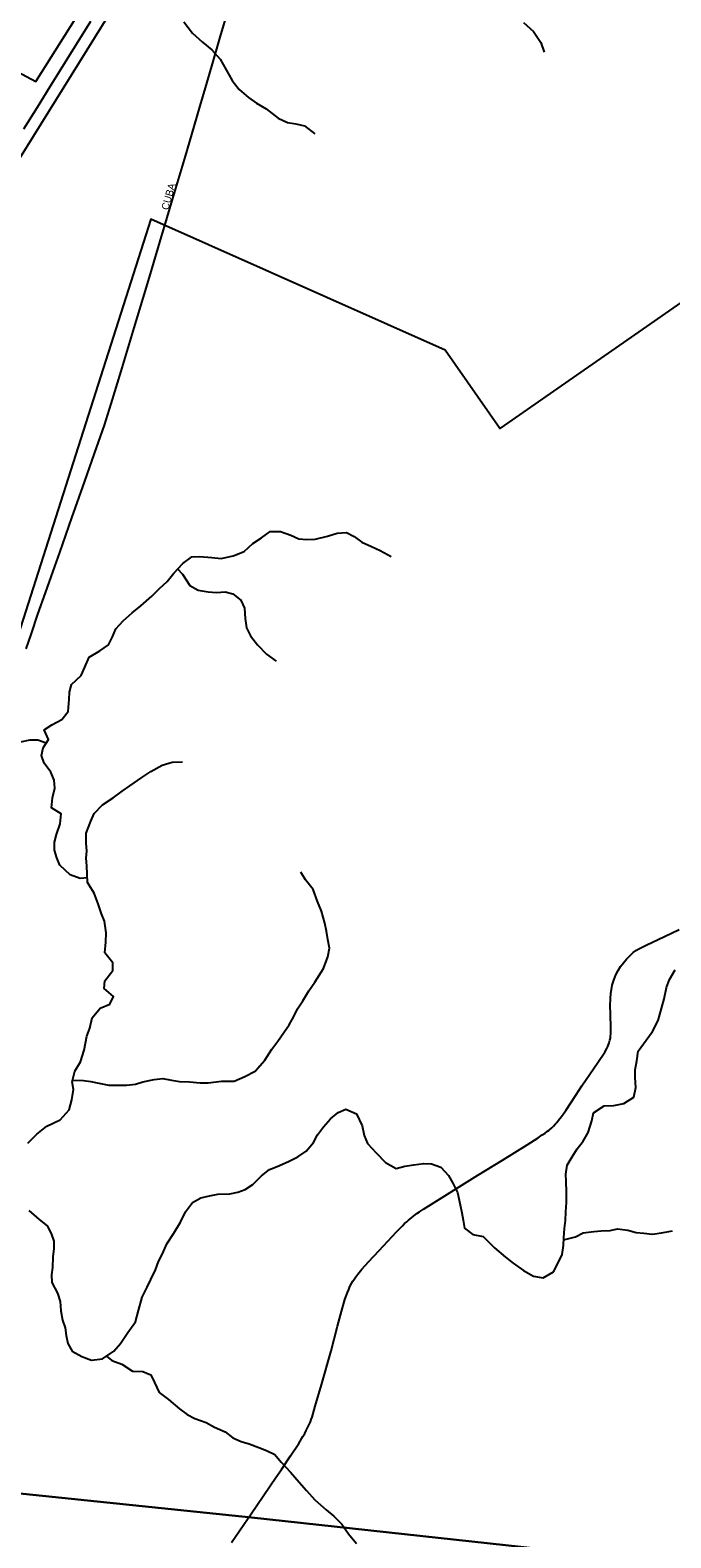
# Model space of a CAD drawing. Extents: x 1442749 to 1756758, y 235267 to 677782.
# Drawn here: x 1590164 to 1594524, y 510563 to 520821 of the extents above; entities that cross this region are included whole.
import ezdxf

# ---------------------------------------------------------------- set-up
doc = ezdxf.new("R2010")
doc.units = 0
for name, color, linetype in [('GM_X_City_Street', 7, 'Continuous'), ('GM_X_City_Street_Text', 7, 'Continuous'), ('GM_X_Corporation', 7, 'Continuous'), ('GM_X_County_Road', 7, 'Continuous'), ('GM_X_Major_River', 7, 'Continuous'), ('GM_X_Minor_River', 7, 'Continuous'), ('GM_X_Rail_Line', 7, 'Continuous'), ('GM_X_Township', 7, 'Continuous'), ('GM_X_Township_Road', 7, 'Continuous'), ('GM_X_US_Route', 7, 'Continuous')]:
    doc.layers.add(name, color=color, linetype=linetype)

msp = doc.modelspace()

# ---------------------------------------------------------------- linework, layer by layer
at = {"layer": 'GM_X_City_Street'}
msp.add_lwpolyline([(1591085, 519508), (1591125, 519647), (1591221, 519964), (1591279, 520166), (1591320, 520305), (1591356, 520428), (1591399, 520576), (1591457, 520774), (1591513, 520963)], dxfattribs=at)
at = {"layer": 'GM_X_Corporation'}
for points in [[(1600054, 522300), (1597344, 518704), (1597384, 518674), (1597022, 518194), (1596857, 518034), (1596225, 518761), (1595739, 518727), (1595708, 518852), (1595571, 518899), (1595536, 518975), (1595389, 518924), (1595223, 519406), (1593360, 518111), (1592987, 518643), (1590986, 519534), (1589824, 515905)], [(1589913, 520625), (1590202, 520471), (1591134, 521952)]]:
    msp.add_lwpolyline(points, dxfattribs=at)
at = {"layer": 'GM_X_County_Road'}
msp.add_lwpolyline([(1590136, 516611), (1590172, 516717), (1590217, 516847), (1590269, 516992), (1590321, 517141), (1590365, 517268), (1590448, 517503), (1590522, 517713), (1590616, 517979), (1590669, 518134), (1590715, 518278), (1590782, 518501), (1590872, 518796), (1590956, 519072), (1590994, 519201), (1591058, 519418), (1591085, 519508)], dxfattribs=at)
at = {"layer": 'GM_X_Major_River'}
for points in [[(1594203, 513518), (1594271, 513562), (1594286, 513626), (1594281, 513695), (1594281, 513747), (1594292, 513809), (1594301, 513875), (1594355, 513950), (1594398, 514007), (1594438, 514083), (1594460, 514165), (1594478, 514231), (1594495, 514308), (1594514, 514362), (1594554, 514428)], [(1590325, 512582), (1590324, 512532), (1590318, 512475), (1590315, 512403), (1590308, 512353), (1590311, 512301), (1590349, 512228), (1590368, 512171), (1590373, 512107), (1590383, 512043), (1590402, 511992), (1590409, 511940), (1590420, 511885), (1590449, 511832), (1590516, 511797), (1590582, 511771), (1590656, 511782), (1590733, 511834), (1590779, 511886), (1590828, 511959), (1590880, 512032), (1590902, 512110), (1590926, 512200), (1590959, 512269), (1590984, 512321), (1591016, 512387), (1591037, 512444), (1591064, 512496), (1591094, 512564), (1591142, 512635), (1591187, 512710), (1591221, 512780), (1591269, 512845), (1591325, 512876), (1591384, 512891), (1591442, 512901), (1591522, 512904), (1591577, 512915), (1591627, 512934), (1591678, 512967), (1591739, 513026), (1591793, 513069), (1591845, 513090), (1591922, 513124), (1591985, 513155), (1592042, 513194), (1592091, 513253), (1592120, 513305), (1592160, 513360), (1592207, 513413), (1592260, 513458), (1592313, 513479), (1592384, 513448), (1592422, 513367), (1592437, 513300), (1592460, 513245), (1592519, 513182), (1592581, 513116), (1592654, 513077), (1592713, 513091), (1592775, 513102), (1592842, 513111), (1592894, 513108), (1592959, 513084), (1593010, 513029), (1593041, 512976), (1593072, 512913), (1593090, 512829), (1593101, 512774), (1593110, 512724), (1593119, 512671), (1593176, 512628), (1593246, 512613), (1593324, 512537), (1593399, 512473), (1593450, 512432), (1593521, 512382), (1593590, 512344), (1593654, 512331), (1593725, 512374), (1593757, 512433), (1593784, 512491), (1593793, 512551), (1593795, 512605), (1593800, 512667), (1593807, 512723), (1593810, 512781), (1593814, 512845), (1593813, 512918), (1593811, 512988), (1593810, 513038), (1593819, 513098), (1593853, 513156), (1593886, 513209), (1593927, 513263), (1593961, 513322), (1593986, 513400), (1593998, 513454), (1594069, 513502), (1594135, 513505), (1594203, 513518)], [(1590155, 512790), (1590226, 512730), (1590279, 512685), (1590306, 512634), (1590325, 512582)]]:
    msp.add_lwpolyline(points, dxfattribs=at)
at = {"layer": 'GM_X_Minor_River'}
for points in [[(1591209, 520878), (1591269, 520801), (1591336, 520740), (1591401, 520687), (1591457, 520623), (1591498, 520552), (1591539, 520479), (1591585, 520417), (1591650, 520362), (1591704, 520325), (1591770, 520286), (1591851, 520223), (1591915, 520192), (1591971, 520183), (1592031, 520169), (1592102, 520116)], [(1593522, 520872), (1593590, 520811), (1593639, 520738), (1593662, 520672)], [(1590553, 515053), (1590503, 515049), (1590435, 515074), (1590366, 515139), (1590346, 515189), (1590329, 515242), (1590329, 515296), (1590342, 515348), (1590367, 515422), (1590374, 515490), (1590308, 515529), (1590315, 515599), (1590332, 515663), (1590326, 515719), (1590305, 515772), (1590258, 515834), (1590240, 515887), (1590253, 515939), (1590288, 515994), (1590260, 516061), (1590311, 516094), (1590379, 516130), (1590422, 516185), (1590429, 516266), (1590432, 516316), (1590446, 516368), (1590511, 516431), (1590536, 516487), (1590565, 516555), (1590637, 516598), (1590696, 516640), (1590723, 516694), (1590747, 516747), (1590796, 516803), (1590859, 516856), (1590918, 516904), (1590991, 516969), (1591045, 517023), (1591096, 517070), (1591141, 517126), (1591202, 517193), (1591264, 517237), (1591316, 517240), (1591401, 517233), (1591463, 517227), (1591545, 517244), (1591620, 517275), (1591678, 517328), (1591737, 517368), (1591796, 517411), (1591868, 517409), (1591937, 517384), (1591991, 517361), (1592047, 517356), (1592104, 517358), (1592188, 517379), (1592254, 517398), (1592317, 517403), (1592368, 517375), (1592420, 517338), (1592486, 517307), (1592546, 517280), (1592621, 517241)], [(1591167, 517155), (1591201, 517119), (1591250, 517042), (1591308, 517010), (1591374, 516999), (1591432, 516994), (1591490, 517000), (1591542, 516985), (1591598, 516942), (1591623, 516888), (1591628, 516818), (1591635, 516755), (1591663, 516699), (1591710, 516638), (1591772, 516575), (1591837, 516528)], [(1590272, 515970), (1590217, 515991), (1590161, 515990), (1590095, 515977), (1590027, 516003), (1589953, 516052), (1589900, 516079), (1589820, 516088), (1589755, 516079), (1589692, 516130), (1589624, 516148), (1589566, 516163), (1589510, 516168), (1589458, 516172), (1589404, 516181), (1589348, 516184), (1589290, 516188), (1589228, 516187), (1589177, 516186), (1589125, 516182), (1589067, 516205), (1589000, 516242), (1588928, 516277), (1588858, 516292)], [(1590147, 513248), (1590209, 513310), (1590278, 513363), (1590367, 513406), (1590430, 513474), (1590447, 513544), (1590458, 513614), (1590450, 513666), (1590467, 513738), (1590506, 513802), (1590531, 513882), (1590550, 513976), (1590569, 514030), (1590586, 514102), (1590641, 514167), (1590707, 514193), (1590730, 514246), (1590668, 514301), (1590673, 514353), (1590726, 514423), (1590726, 514475), (1590673, 514544), (1590678, 514616), (1590681, 514680), (1590670, 514759), (1590650, 514809), (1590627, 514877), (1590600, 514950), (1590555, 515021), (1590551, 515079), (1590550, 515135), (1590546, 515187), (1590549, 515237), (1590546, 515289), (1590544, 515358), (1590576, 515440), (1590600, 515491), (1590657, 515551), (1590728, 515598), (1590790, 515644), (1590843, 515679), (1590924, 515736), (1590986, 515778), (1591061, 515821), (1591131, 515840), (1591200, 515842)], [(1590453, 513678), (1590526, 513675), (1590576, 513667), (1590632, 513656), (1590698, 513643), (1590819, 513642), (1590881, 513649), (1590931, 513666), (1591008, 513682), (1591066, 513689), (1591126, 513678), (1591180, 513668), (1591248, 513665), (1591320, 513658), (1591374, 513659), (1591466, 513670), (1591551, 513671), (1591625, 513703), (1591696, 513738), (1591761, 513813), (1591808, 513889), (1591850, 513943), (1591889, 514002), (1591926, 514054), (1591959, 514110), (1591983, 514162), (1592020, 514216), (1592061, 514285), (1592102, 514343), (1592159, 514437), (1592190, 514517), (1592201, 514575), (1592189, 514635), (1592180, 514691), (1592169, 514745), (1592146, 514826), (1592120, 514892), (1592089, 514975), (1592038, 515040), (1592006, 515092)], [(1593794, 512591), (1593875, 512612), (1593927, 512639), (1594000, 512647), (1594050, 512652), (1594110, 512655), (1594160, 512665), (1594232, 512656), (1594288, 512641), (1594340, 512637), (1594398, 512630), (1594459, 512639), (1594535, 512652)], [(1590683, 511800), (1590720, 511769), (1590788, 511745), (1590860, 511698), (1590930, 511695), (1590984, 511672), (1591011, 511620), (1591042, 511551), (1591106, 511504), (1591179, 511441), (1591233, 511403), (1591285, 511374), (1591361, 511347), (1591418, 511316), (1591490, 511285), (1591542, 511243), (1591600, 511218), (1591655, 511203), (1591721, 511178), (1591773, 511158), (1591829, 511129), (1591872, 511078), (1591936, 511011), (1591995, 510941), (1592045, 510886), (1592100, 510821), (1592177, 510754), (1592231, 510711), (1592284, 510656), (1592330, 510590), (1592385, 510525)]]:
    msp.add_lwpolyline(points, dxfattribs=at)
at = {"layer": 'GM_X_Rail_Line'}
msp.add_lwpolyline([(1589373, 518794), (1591416, 522079)], dxfattribs=at)
at = {"layer": 'GM_X_Township'}
for points in [[(1607409, 509023), (1601349, 509660), (1598207, 509991), (1595438, 510291), (1595355, 510300), (1591670, 510701), (1587291, 511156), (1584741, 511410), (1583705, 511521), (1580873, 511825), (1577466, 512312), (1577336, 518378), (1577247, 522507)], [(1573762, 498986), (1574679, 502300), (1575144, 503972), (1577400, 512074), (1577466, 512312), (1580873, 511825), (1583705, 511521), (1584741, 511410), (1587291, 511156), (1591670, 510701), (1595355, 510300), (1595438, 510291), (1598207, 509991), (1601349, 509660), (1607409, 509023), (1609267, 508822), (1609586, 508788), (1610595, 504741), (1611751, 500101)]]:
    msp.add_lwpolyline(points, dxfattribs=at)
at = {"layer": 'GM_X_Township_Road'}
for points in [[(1591667, 510727), (1591836, 510974), (1591874, 511028), (1591935, 511121), (1591991, 511206), (1592020, 511253), (1592032, 511273), (1592043, 511293), (1592052, 511311), (1592061, 511329), (1592071, 511353), (1592076, 511368), (1592082, 511385), (1592104, 511460), (1592146, 511605), (1592211, 511836), (1592255, 512004), (1592282, 512102), (1592306, 512184), (1592317, 512214), (1592323, 512233), (1592332, 512253), (1592340, 512272), (1592351, 512293), (1592360, 512309), (1592370, 512325), (1592379, 512339), (1592393, 512357), (1592420, 512390), (1592466, 512440), (1592538, 512517), (1592656, 512645), (1592677, 512666), (1592697, 512687), (1592712, 512701), (1592726, 512714), (1592739, 512725), (1592758, 512741), (1592775, 512754), (1592794, 512769), (1592813, 512782), (1592840, 512800), (1592931, 512857), (1593138, 512985), (1593210, 513030), (1593378, 513133), (1593545, 513237), (1593620, 513284), (1593649, 513304), (1593669, 513317), (1593684, 513329), (1593695, 513337), (1593713, 513353), (1593725, 513365), (1593738, 513379), (1593747, 513389), (1593760, 513404), (1593780, 513430), (1593808, 513471), (1593876, 513575), (1593917, 513638), (1594026, 513797), (1594045, 513824), (1594057, 513841), (1594075, 513868), (1594088, 513893), (1594095, 513906), (1594104, 513930), (1594109, 513948), (1594112, 513963), (1594114, 513977), (1594116, 513994), (1594116, 514012), (1594116, 514033), (1594112, 514125), (1594110, 514184), (1594112, 514230), (1594115, 514269), (1594119, 514294), (1594125, 514323), (1594136, 514357), (1594150, 514393), (1594165, 514422), (1594182, 514450), (1594201, 514476), (1594222, 514500), (1594244, 514524), (1594268, 514545), (1594289, 514561), (1594305, 514571), (1594355, 514596), (1594480, 514654), (1594580, 514703)], [(1591535, 510532), (1591618, 510654), (1591667, 510727)]]:
    msp.add_lwpolyline(points, dxfattribs=at)
at = {"layer": 'GM_X_US_Route'}
msp.add_lwpolyline([(1590121, 520150), (1590213, 520297), (1590299, 520438), (1590479, 520725), (1590576, 520883)], dxfattribs=at)

# ---------------------------------------------------------------- texts
at = {"layer": 'GM_X_City_Street_Text'}
msp.add_text('CUBA', height=50, rotation=73.8565, dxfattribs=at).set_placement((1591103, 519593))

doc.saveas('drawing.dxf')
